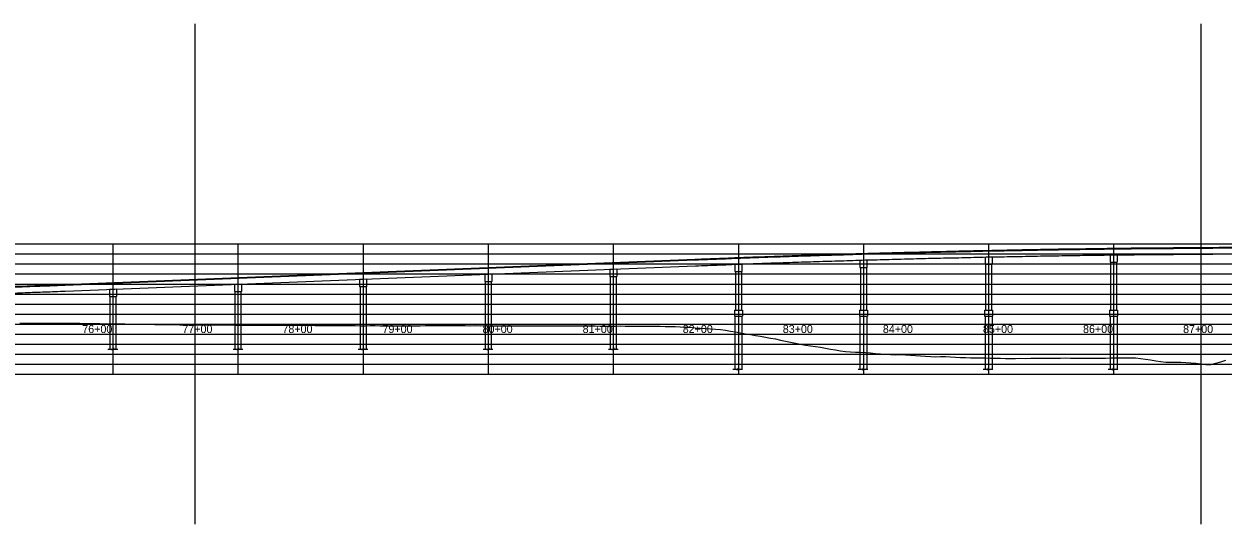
# Model space of a CAD drawing. Extents: x -464 to 4306, y -1372 to 300.
# Drawn here: x 754 to 1952, y -200 to 300 of the extents above; entities that cross this region are included whole.
import ezdxf

# ---------------------------------------------------------------- set-up
doc = ezdxf.new("R2010")
doc.units = 0
for name, color, linetype in [('BR_AUTO DIMENSION', 7, 'Continuous'), ('BR_GRID LINES', 7, 'Continuous'), ('Default', 7, 'Continuous'), ('Mis Ground Lines', 7, 'Continuous'), ('NOPLOT', 7, 'Continuous'), ('sub interior bent cap lines', 7, 'Continuous'), ('Sup Concrete Girder Lines', 7, 'Continuous'), ('Sup Concrete Slab Lines', 7, 'Continuous')]:
    doc.layers.add(name, color=color, linetype=linetype)

msp = doc.modelspace()

# ---------------------------------------------------------------- linework, layer by layer
at = {"layer": 'BR_AUTO DIMENSION'}
for points in [[(837.8, -25), (842.1, -25), (842.1, -26.1), (843.2, -23.9), (843.2, -25), (847.5, -25)], [(962.8, -25), (967.1, -25), (967.1, -26.1), (968.2, -23.9), (968.2, -25), (972.5, -25)], [(1087.8, -25), (1092.1, -25), (1092.1, -26.1), (1093.2, -23.9), (1093.2, -25), (1097.5, -25)], [(1212.8, -25), (1217.1, -25), (1217.1, -26.1), (1218.2, -23.9), (1218.2, -25), (1222.5, -25)], [(1337.8, -25), (1342.1, -25), (1342.1, -26.1), (1343.2, -23.9), (1343.2, -25), (1347.5, -25)], [(1462.3, -45), (1466.6, -45), (1466.6, -46.1), (1467.7, -43.9), (1467.7, -45), (1472, -45)], [(1587.3, -45), (1591.6, -45), (1591.6, -46.1), (1592.7, -43.9), (1592.7, -45), (1597, -45)], [(1712.3, -45), (1716.6, -45), (1716.6, -46.1), (1717.7, -43.9), (1717.7, -45), (1722, -45)], [(1837.3, -45), (1841.6, -45), (1841.6, -46.1), (1842.7, -43.9), (1842.7, -45), (1847, -45)]]:
    msp.add_lwpolyline(points, dxfattribs=at)
at = {"layer": 'BR_GRID LINES'}
for p, q in [((924.7, 300), (924.7, -200)), ((1929.7, 300), (1929.7, -200)), ((-80.3, 80), (3939.7, 80)), ((-80.3, 70), (3939.7, 70)), ((-80.3, 60), (3939.7, 60)), ((-80.3, 50), (3939.7, 50)), ((-80.3, 40), (3939.7, 40)), ((-80.3, 30), (3939.7, 30)), ((-80.3, 20), (3939.7, 20)), ((-80.3, 10), (3939.7, 10)), ((-80.3, 0), (3939.7, 0)), ((-80.3, -10), (3939.7, -10)), ((-80.3, -20), (3939.7, -20)), ((-80.3, -30), (3939.7, -30)), ((-80.3, -40), (3939.7, -40)), ((-80.3, -50), (3939.7, -50))]:
    msp.add_line(p, q, dxfattribs=at)
at = {"layer": 'Default'}
for p, q in [((842.7, 80), (842.7, -50)), ((967.7, 80), (967.7, -50)), ((1092.7, 80), (1092.7, -50)), ((1217.7, 80), (1217.7, -50)), ((1342.7, 80), (1342.7, -50)), ((1467.7, 80), (1467.7, -50)), ((1592.7, 80), (1592.7, -50)), ((1717.7, 80), (1717.7, -50)), ((1842.7, 80), (1842.7, -50)), ((-170.3, 0), (4029.7, 0))]:
    msp.add_line(p, q, dxfattribs=at)
at = {"layer": 'Mis Ground Lines'}
for points in [[(749.7, 0.9), (754.7, 0.9), (759.7, 0.9), (764.7, 0.9), (769.7, 0.9), (774.7, 0.9), (779.7, 0.9), (784.7, 0.9), (789.7, 0.8), (794.7, 0.8), (799.7, 0.8), (804.7, 0.7), (809.7, 0.7), (814.7, 0.6), (819.7, 0.5), (824.7, 0.5), (829.7, 0.4), (834.7, 0.3), (839.7, 0.3), (844.7, 0.2), (849.7, 0.1), (854.7, 0.1), (859.7, 0), (864.7, -0.1), (869.7, -0.1), (874.7, -0.2), (879.7, -0.3), (884.7, -0.4), (889.7, -0.4), (894.7, -0.5), (899.7, -0.6), (904.7, -0.6), (909.7, -0.7), (914.7, -0.8), (919.7, -0.8), (924.7, -0.9), (929.7, -0.9), (934.7, -0.9), (939.7, -0.9), (944.7, -0.9), (949.7, -0.9), (954.7, -0.9), (959.7, -0.9), (964.7, -1), (969.7, -1), (974.7, -1), (979.7, -1), (984.7, -1), (989.7, -1), (994.7, -1), (999.7, -1), (1004.7, -1), (1009.7, -1.1), (1014.7, -1.1), (1019.7, -1.1), (1024.7, -1.2), (1029.7, -1.2), (1034.7, -1.4), (1039.7, -1.3), (1044.7, -1.5), (1049.7, -1.5), (1054.7, -1.4), (1059.7, -1.4), (1064.7, -1.5), (1069.7, -1.5), (1074.7, -1.6), (1079.7, -1.6), (1084.7, -1.6), (1089.7, -1.7), (1094.7, -1.7), (1099.7, -1.6), (1104.7, -1.6), (1109.7, -1.7), (1114.7, -1.7), (1119.7, -1.7), (1124.7, -1.7), (1129.7, -1.7), (1134.7, -1.7), (1139.7, -1.7), (1144.7, -1.7), (1149.7, -1.7), (1154.7, -1.6), (1159.7, -1.6), (1164.7, -1.6), (1169.7, -1.5), (1174.7, -1.5), (1179.7, -1.5), (1184.7, -1.5), (1189.7, -1.6), (1194.7, -1.6), (1199.7, -1.7), (1204.7, -1.6), (1209.7, -1.7), (1214.7, -1.6), (1219.7, -1.7), (1224.7, -1.7), (1229.7, -1.8)], [(1229.7, -1.8), (1234.7, -1.8), (1239.7, -1.8), (1244.7, -1.8), (1249.7, -1.8), (1254.7, -1.8), (1259.7, -1.8), (1264.7, -1.7), (1269.7, -1.8), (1274.7, -1.8), (1279.7, -1.8), (1284.7, -1.9), (1289.7, -1.9), (1294.7, -1.9), (1299.7, -1.8), (1304.7, -1.9), (1309.7, -1.8), (1314.7, -1.9), (1319.7, -1.9), (1324.7, -1.9), (1329.7, -2), (1334.7, -2), (1339.7, -2), (1344.7, -2), (1349.7, -1.9), (1354.7, -2), (1359.7, -2), (1364.7, -2.1), (1369.7, -2.2), (1374.7, -2.2), (1379.7, -2.3), (1384.7, -2.2), (1389.7, -2.3), (1394.7, -2.4), (1399.7, -2.5), (1404.7, -2.6), (1409.7, -2.8), (1414.7, -3), (1419.7, -3.2), (1424.7, -3.8), (1429.7, -4.2), (1434.7, -4.5), (1439.7, -4.9), (1444.7, -5.3), (1449.7, -5.6), (1454.7, -6.2), (1459.7, -7), (1464.7, -7.8), (1469.7, -8.7), (1474.7, -9.7), (1479.7, -10.6), (1484.7, -11.5), (1489.7, -12.3), (1494.7, -13.1), (1499.7, -14), (1504.7, -14.9), (1509.7, -16), (1514.7, -17.2), (1519.7, -18.3), (1524.7, -19.3), (1529.7, -20.3), (1534.7, -21.2), (1539.7, -21.9), (1544.7, -22.5), (1549.7, -23.1), (1554.7, -24.2), (1559.7, -25), (1564.7, -25.9), (1569.7, -26.9), (1574.7, -27.4), (1579.7, -27.8), (1584.7, -28.2), (1589.7, -28.1), (1594.7, -28.4), (1599.7, -28.9), (1604.7, -29.5), (1609.7, -29.9), (1614.7, -30.3), (1619.7, -30.6), (1624.7, -30.7), (1629.7, -30.6), (1634.7, -30.8), (1639.7, -31.2), (1644.7, -31.5), (1649.7, -31.9), (1654.7, -32.3), (1659.7, -32.4), (1664.7, -32.7), (1669.7, -32.5), (1674.7, -32.6), (1679.7, -32.8), (1684.7, -33), (1689.7, -33.4), (1694.7, -33.6), (1699.7, -33.7), (1704.7, -33.8), (1709.7, -33.9), (1714.7, -33.9), (1719.7, -34), (1724.7, -34.1), (1729.7, -34.3)], [(1729.7, -34.3), (1734.7, -34.5), (1739.7, -34.6), (1744.7, -34.5), (1749.7, -34.3), (1754.7, -34.4), (1759.7, -34.3), (1764.7, -34.2), (1769.7, -34.3), (1774.7, -34.2), (1779.7, -34.1), (1784.7, -34.2), (1789.7, -34.2), (1794.7, -33.9), (1799.7, -34.1), (1804.7, -34.1), (1809.7, -34.3), (1814.7, -34.3), (1819.7, -34.3), (1824.7, -34.2), (1829.7, -34.2), (1834.7, -34), (1839.7, -33.8), (1844.7, -33.8), (1849.7, -33.7), (1854.7, -33.8), (1859.7, -33.7), (1864.7, -33.9), (1869.7, -34.5), (1874.7, -35.3), (1879.7, -35.9), (1884.7, -36.7), (1889.7, -37.5), (1894.7, -38.3), (1899.7, -38.2), (1904.7, -38), (1909.7, -38.1), (1914.7, -38.5), (1919.7, -38.8), (1924.7, -39.1), (1929.7, -39.7), (1934.7, -40.4), (1939.7, -40.5), (1944.7, -39.3), (1949.7, -37.9), (1954.7, -36.3)]]:
    msp.add_lwpolyline(points, dxfattribs=at)
at = {"layer": 'sub interior bent cap lines'}
for p, q in [((1596.2, 63.7), (1589.2, 63.5)), ((1589.2, 63.5), (1589.2, 56.6)), ((1596.2, 63.7), (1596.2, 56.6)), ((1721.2, 66.8), (1714.2, 66.6)), ((1714.2, 66.6), (1714.2, 59.7)), ((1721.2, 66.8), (1721.2, 59.7)), ((1846.2, 68.8), (1839.2, 68.7)), ((1839.2, 68.7), (1839.2, 61.7)), ((1839.2, 61.7), (1846.2, 61.7)), ((1839.7, 61.7), (1839.7, 14)), ((1845.7, 61.7), (1845.7, 14)), ((1846.2, 68.8), (1846.2, 61.7)), ((1221.2, 49.7), (1214.2, 49.4)), ((1214.2, 49.4), (1214.2, 42.5)), ((1221.2, 49.7), (1221.2, 42.5)), ((1346.2, 54.7), (1339.2, 54.4)), ((1339.2, 54.4), (1339.2, 47.5)), ((1346.2, 54.7), (1346.2, 47.5)), ((1471.2, 59.6), (1464.2, 59.3)), ((1464.2, 59.3), (1464.2, 52.5)), ((1464.2, 52.5), (1471.2, 52.5)), ((1464.7, 52.5), (1464.7, 14)), ((1470.7, 52.5), (1470.7, 14)), ((1471.2, 59.6), (1471.2, 52.5)), ((1589.2, 56.6), (1596.2, 56.6)), ((1589.7, 56.6), (1589.7, 14)), ((1595.7, 56.6), (1595.7, 14)), ((1714.2, 59.7), (1721.2, 59.7)), ((1714.7, 59.7), (1714.7, 14)), ((1720.7, 59.7), (1720.7, 14)), ((971.2, 39.7), (964.2, 39.4)), ((964.2, 39.4), (964.2, 32.5)), ((971.2, 39.7), (971.2, 32.5)), ((1096.2, 44.7), (1089.2, 44.4)), ((1089.2, 44.4), (1089.2, 37.5)), ((1089.2, 37.5), (1096.2, 37.5)), ((1089.7, 37.5), (1089.7, -25)), ((1095.7, 37.5), (1095.7, -25)), ((1096.2, 44.7), (1096.2, 37.5)), ((1214.2, 42.5), (1221.2, 42.5)), ((1214.7, 42.5), (1214.7, -25)), ((1220.7, 42.5), (1220.7, -25)), ((1339.2, 47.5), (1346.2, 47.5)), ((1339.7, 47.5), (1339.7, -25)), ((1345.7, 47.5), (1345.7, -25)), ((846.2, 34.7), (839.2, 34.4)), ((839.2, 34.4), (839.2, 27.5)), ((839.2, 27.5), (846.2, 27.5)), ((839.7, 27.5), (839.7, -25)), ((845.7, 27.5), (845.7, -25)), ((846.2, 34.7), (846.2, 27.5)), ((964.2, 32.5), (971.2, 32.5)), ((964.7, 32.5), (964.7, -25)), ((970.7, 32.5), (970.7, -25)), ((1463.7, 14), (1471.7, 14)), ((1463.7, 14), (1463.7, 8)), ((1471.7, 14), (1471.7, 8)), ((1588.7, 14), (1596.7, 14)), ((1588.7, 14), (1588.7, 8)), ((1596.7, 14), (1596.7, 8)), ((1713.7, 14), (1721.7, 14)), ((1713.7, 14), (1713.7, 8)), ((1721.7, 14), (1721.7, 8)), ((1838.7, 14), (1846.7, 14)), ((1838.7, 14), (1838.7, 8)), ((1846.7, 14), (1846.7, 8)), ((1463.7, 8), (1471.7, 8)), ((1464.2, 8), (1464.2, -45)), ((1471.2, 8), (1471.2, -45)), ((1588.7, 8), (1596.7, 8)), ((1589.2, 8), (1589.2, -45)), ((1596.2, 8), (1596.2, -45)), ((1713.7, 8), (1721.7, 8)), ((1714.2, 8), (1714.2, -45)), ((1721.2, 8), (1721.2, -45)), ((1838.7, 8), (1846.7, 8)), ((1839.2, 8), (1839.2, -45)), ((1846.2, 8), (1846.2, -45))]:
    msp.add_line(p, q, dxfattribs=at)
at = {"layer": 'Sup Concrete Girder Lines'}
for p, q in [((794.7, 38.9), (1424.7, 64.1)), ((794.9, 32.9), (1424.9, 58.1))]:
    msp.add_line(p, q, dxfattribs=at)
for points in [[(1424.7, 64.1), (1448.9, 65.1), (1473.1, 66), (1497.3, 66.9), (1521.5, 67.7), (1545.7, 68.5), (1569.9, 69.2), (1594.1, 70), (1618.3, 70.6), (1642.5, 71.3), (1666.7, 71.9), (1690.9, 72.4), (1715.1, 73), (1739.3, 73.4), (1763.5, 73.9), (1787.7, 74.3), (1811.9, 74.7), (1836.1, 75), (1860.3, 75.3), (1884.5, 75.5), (1908.7, 75.7), (1932.9, 75.9), (1957.1, 76.1), (1981.3, 76.2), (2005.5, 76.2), (2029.7, 76.2), (2053.9, 76.2), (2078.1, 76.2), (2102.3, 76.1), (2126.5, 75.9), (2150.7, 75.7), (2174.9, 75.5), (2199.1, 75.3), (2223.3, 75), (2247.5, 74.7), (2271.7, 74.3), (2295.9, 73.9), (2320.1, 73.4), (2344.3, 73), (2368.5, 72.4), (2392.7, 71.9), (2416.9, 71.3), (2441.1, 70.6), (2465.3, 70), (2489.5, 69.2), (2513.7, 68.5), (2537.8, 67.7), (2562, 66.9), (2586.2, 66), (2610.4, 65.1), (2634.6, 64.1)], [(1424.9, 58.1), (1449.1, 59.1), (1473.3, 60), (1497.5, 60.9), (1521.7, 61.7), (1545.9, 62.5), (1570.1, 63.2), (1594.3, 64), (1618.5, 64.6), (1642.6, 65.3), (1666.8, 65.9), (1691, 66.4), (1715.2, 67), (1739.4, 67.4), (1763.6, 67.9), (1787.8, 68.3), (1812, 68.7), (1836.2, 69), (1860.3, 69.3), (1884.5, 69.5), (1908.7, 69.7), (1932.9, 69.9), (1957.1, 70.1), (1981.3, 70.2), (2005.5, 70.2), (2029.7, 70.2), (2053.9, 70.2), (2078.1, 70.2), (2102.2, 70.1), (2126.4, 69.9), (2150.6, 69.7), (2174.8, 69.5), (2199, 69.3), (2223.2, 69), (2247.4, 68.7), (2271.6, 68.3), (2295.8, 67.9), (2319.9, 67.4), (2344.1, 67), (2368.3, 66.4), (2392.5, 65.9), (2416.7, 65.3), (2440.9, 64.6), (2465.1, 64), (2489.3, 63.2), (2513.5, 62.5), (2537.6, 61.7), (2561.8, 60.9), (2586, 60), (2610.2, 59.1), (2634.4, 58.1)], [(294.7, 24.6), (304.7, 24.8), (314.7, 25), (324.7, 25.2), (334.7, 25.4), (344.7, 25.5), (354.7, 25.7), (364.7, 25.9), (374.7, 26.1), (384.7, 26.4), (394.7, 26.6), (404.7, 26.8), (414.7, 27), (424.7, 27.2), (434.7, 27.5), (444.7, 27.7), (454.7, 28), (464.7, 28.2), (474.7, 28.5), (484.7, 28.7), (494.7, 29), (504.7, 29.2), (514.7, 29.5), (524.7, 29.8), (534.7, 30.1), (544.7, 30.4), (554.7, 30.6), (564.7, 30.9), (574.7, 31.2), (584.7, 31.5), (594.7, 31.8), (604.7, 32.2), (614.7, 32.5), (624.7, 32.8), (634.7, 33.1), (644.7, 33.4), (654.7, 33.8), (664.7, 34.1), (674.7, 34.5), (684.7, 34.8), (694.7, 35.2), (704.7, 35.5), (714.7, 35.9), (724.7, 36.2), (734.7, 36.6), (744.7, 37), (754.7, 37.4), (764.7, 37.8), (774.7, 38.1), (784.7, 38.5), (794.7, 38.9)], [(294.8, 18.6), (304.8, 18.8), (314.8, 19), (324.8, 19.2), (334.8, 19.4), (344.8, 19.5), (354.8, 19.7), (364.8, 19.9), (374.8, 20.2), (384.8, 20.4), (394.8, 20.6), (404.8, 20.8), (414.8, 21), (424.8, 21.3), (434.8, 21.5), (444.8, 21.7), (454.8, 22), (464.8, 22.2), (474.8, 22.5), (484.8, 22.7), (494.8, 23), (504.9, 23.3), (514.9, 23.5), (524.9, 23.8), (534.9, 24.1), (544.9, 24.4), (554.9, 24.6), (564.9, 24.9), (574.9, 25.2), (584.9, 25.5), (594.9, 25.8), (604.9, 26.2), (614.9, 26.5), (624.9, 26.8), (634.9, 27.1), (644.9, 27.4), (654.9, 27.8), (664.9, 28.1), (674.9, 28.5), (684.9, 28.8), (694.9, 29.2), (704.9, 29.5), (714.9, 29.9), (724.9, 30.2), (734.9, 30.6), (744.9, 31), (754.9, 31.4), (764.9, 31.8), (774.9, 32.1), (784.9, 32.5), (794.9, 32.9)]]:
    msp.add_spline(points, degree=3, dxfattribs=at)
at = {"layer": 'Sup Concrete Slab Lines'}
msp.add_line((794.7, 39.6), (1424.7, 64.8), dxfattribs=at)
for points in [[(1424.7, 64.8), (1448.9, 65.7), (1473.1, 66.7), (1497.3, 67.5), (1521.5, 68.4), (1545.7, 69.2), (1569.9, 69.9), (1594.1, 70.6), (1618.3, 71.3), (1642.5, 71.9), (1666.7, 72.5), (1690.9, 73.1), (1715.1, 73.6), (1739.3, 74.1), (1763.5, 74.6), (1787.7, 75), (1811.9, 75.3), (1836.1, 75.7), (1860.3, 76), (1884.5, 76.2), (1908.7, 76.4), (1932.9, 76.6), (1957.1, 76.7), (1981.3, 76.8), (2005.5, 76.9), (2029.7, 76.9), (2053.9, 76.9), (2078.1, 76.8), (2102.3, 76.7), (2126.5, 76.6), (2150.7, 76.4), (2174.9, 76.2), (2199.1, 76), (2223.3, 75.7), (2247.5, 75.3), (2271.7, 75), (2295.9, 74.6), (2320.1, 74.1), (2344.3, 73.6), (2368.5, 73.1), (2392.7, 72.5), (2416.9, 71.9), (2441.1, 71.3), (2465.3, 70.6), (2489.5, 69.9), (2513.7, 69.2), (2537.9, 68.4), (2562.1, 67.5), (2586.3, 66.7), (2610.5, 65.7), (2634.7, 64.8)], [(294.7, 25.3), (304.7, 25.5), (314.7, 25.6), (324.7, 25.8), (334.7, 26), (344.7, 26.2), (354.7, 26.4), (364.7, 26.6), (374.7, 26.8), (384.7, 27), (394.7, 27.2), (404.7, 27.5), (414.7, 27.7), (424.7, 27.9), (434.7, 28.2), (444.7, 28.4), (454.7, 28.6), (464.7, 28.9), (474.7, 29.1), (484.7, 29.4), (494.7, 29.6), (504.7, 29.9), (514.7, 30.2), (524.7, 30.5), (534.7, 30.7), (544.7, 31), (554.7, 31.3), (564.7, 31.6), (574.7, 31.9), (584.7, 32.2), (594.7, 32.5), (604.7, 32.8), (614.7, 33.1), (624.7, 33.5), (634.7, 33.8), (644.7, 34.1), (654.7, 34.4), (664.7, 34.8), (674.7, 35.1), (684.7, 35.5), (694.7, 35.8), (704.7, 36.2), (714.7, 36.5), (724.7, 36.9), (734.7, 37.3), (744.7, 37.7), (754.7, 38), (764.7, 38.4), (774.7, 38.8), (784.7, 39.2), (794.7, 39.6)]]:
    msp.add_spline(points, degree=3, dxfattribs=at)

# ---------------------------------------------------------------- texts
at = {"layer": 'NOPLOT'}
for s, p in [('76+00', (812.1, -9)), ('77+00', (912.1, -9)), ('78+00', (1012.1, -9)), ('79+00', (1112.1, -9)), ('80+00', (1212.1, -9)), ('81+00', (1312.1, -9)), ('82+00', (1412.1, -9)), ('83+00', (1512.1, -9)), ('84+00', (1612.1, -9)), ('85+00', (1712.1, -9)), ('86+00', (1812.1, -9)), ('87+00', (1912.1, -9))]:
    msp.add_text(s, height=8, dxfattribs=at).set_placement(p)

doc.saveas('drawing.dxf')
